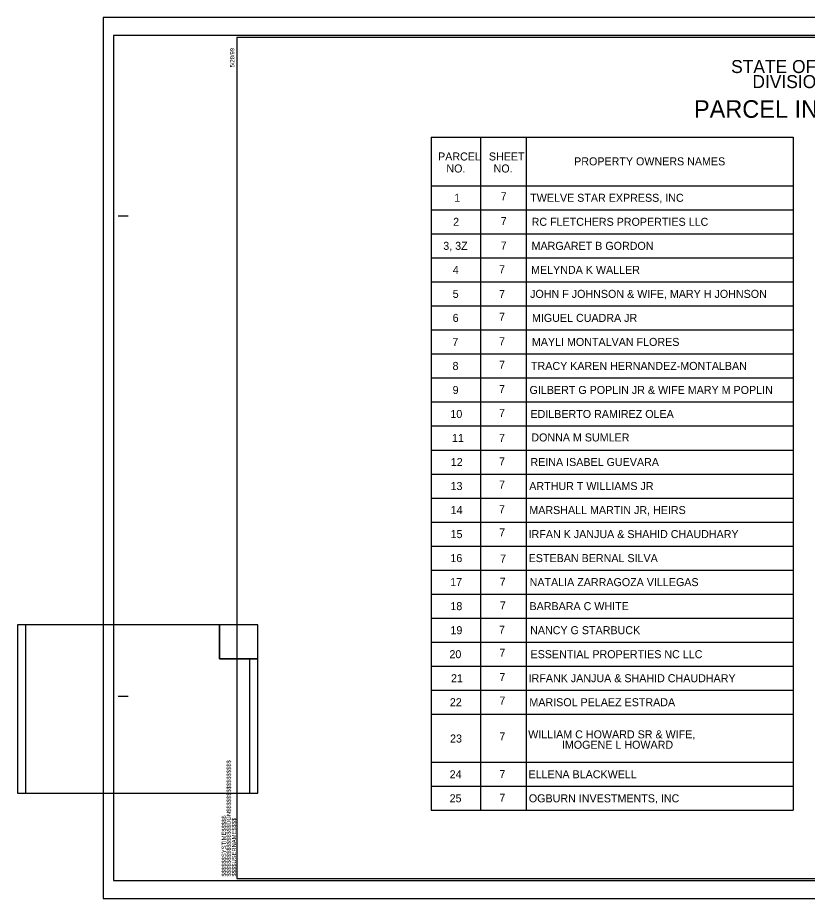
# Model space of a CAD drawing. Extents: x 1729874 to 1731665, y 539736 to 540836.
# Drawn here: x 1729874 to 1730861, y 539736 to 540836 of the extents above; entities that cross this region are included whole.
import ezdxf

# ---------------------------------------------------------------- set-up
doc = ezdxf.new("R2010")
doc.units = 0
for name, color, linetype in [('Sheet Clip Boundary CELL', 7, 'Continuous'), ('Sheet Layout Plan Border', 7, 'Continuous'), ('Sheet Plan Layout CELL', 7, 'Continuous'), ('Sheet Plot Border Inside CELL', 7, 'Continuous'), ('Sheet Plot Border Outside CELL', 7, 'Continuous'), ('Sheet Summary CELL', 7, 'Continuous')]:
    doc.layers.add(name, color=color, linetype=linetype)

msp = doc.modelspace()

# ---------------------------------------------------------------- linework, layer by layer
at = {"layer": 'Sheet Clip Boundary CELL'}
msp.add_lwpolyline([(1729884, 539867.9), (1730164, 539867.9), (1730164, 540035.6), (1730126.1, 540035.6), (1730126.1, 540077.9), (1729884, 540077.9)], close=True, dxfattribs=at)
at = {"layer": 'Sheet Layout Plan Border'}
msp.add_lwpolyline([(1729884, 539867.9), (1730164, 539867.9), (1730164, 540035.6), (1730126.1, 540035.6), (1730126.1, 540077.9), (1729884, 540077.9)], close=True, dxfattribs=at)
at = {"layer": 'Sheet Plan Layout CELL'}
for points in [[(1729874, 540077.9), (1729874, 539867.9), (1730174, 539867.9), (1730174, 540035.6), (1730126.1, 540035.6), (1730126.1, 540077.9)], [(1730126.1, 540035.6), (1730174, 540035.6), (1730174, 540077.9), (1730126.1, 540077.9)]]:
    msp.add_lwpolyline(points, close=True, dxfattribs=at)
at = {"layer": 'Sheet Plot Border Inside CELL'}
msp.add_lwpolyline([(1731660.4, 540813.9), (1729993.9, 540813.9), (1729993.9, 539758.8), (1731660.4, 539758.8)], close=True, dxfattribs=at)
at = {"layer": 'Sheet Plot Border Outside CELL'}
msp.add_lwpolyline([(1731664.9, 540836.3), (1729980.9, 540836.3), (1729980.9, 539736.3), (1731664.9, 539736.3)], close=True, dxfattribs=at)
at = {"layer": 'Sheet Summary CELL'}
for p, q in [((1730147.9, 540811.3), (1730147.9, 540770.9)), ((1730390.5, 540687.2), (1730842.6, 540687.2)), ((1730390.5, 540687.2), (1730777.1, 540687.2)), ((1730390.5, 540687.2), (1730390.5, 539846.3)), ((1730452.1, 540687.2), (1730452.1, 539846.3)), ((1730509.4, 540687.2), (1730509.4, 539846.3)), ((1730842.6, 540687.2), (1730842.6, 539846.3)), ((1730390.5, 540626.3), (1730842.6, 540626.3)), ((1730390.5, 540596.3), (1730842.6, 540596.3)), ((1729999.4, 540588.8), (1730011.9, 540588.8)), ((1730390.5, 540566.3), (1730842.6, 540566.3)), ((1730390.5, 540536.3), (1730842.6, 540536.3)), ((1730390.5, 540506.3), (1730842.6, 540506.3)), ((1730390.5, 540476.3), (1730842.6, 540476.3)), ((1730390.5, 540446.3), (1730842.6, 540446.3)), ((1730390.5, 540416.3), (1730842.6, 540416.3)), ((1730390.5, 540386.3), (1730842.6, 540386.3)), ((1730390.5, 540356.3), (1730842.6, 540356.3)), ((1730390.5, 540326.3), (1730842.6, 540326.3)), ((1730390.5, 540296.3), (1730842.6, 540296.3)), ((1730390.5, 540266.3), (1730842.6, 540266.3)), ((1730390.5, 540236.3), (1730842.6, 540236.3)), ((1730390.5, 540206.3), (1730842.6, 540206.3)), ((1730390.5, 540176.3), (1730842.6, 540176.3)), ((1730390.5, 540146.3), (1730842.6, 540146.3)), ((1730390.5, 540116.3), (1730842.6, 540116.3)), ((1730390.5, 540086.3), (1730842.6, 540086.3)), ((1730390.5, 540056.3), (1730842.6, 540056.3)), ((1730390.5, 540026.3), (1730842.6, 540026.3)), ((1730390.5, 539996.3), (1730842.6, 539996.3)), ((1729999.4, 539988.8), (1730011.9, 539988.8)), ((1730390.5, 539966.3), (1730842.6, 539966.3)), ((1730390.5, 539906.3), (1730842.6, 539906.3)), ((1730390.5, 539876.3), (1730842.6, 539876.3)), ((1730390.5, 539846.3), (1730842.6, 539846.3)), ((1730147.9, 539761.3), (1730147.9, 539761.3)), ((1730147.9, 539761.3), (1730147.9, 539761.3)), ((1730147.9, 539761.3), (1730147.9, 539761.3)), ((1730147.9, 539761.3), (1730147.9, 539761.3)), ((1730147.9, 539761.3), (1730147.9, 539761.3)), ((1730147.9, 539761.3), (1730147.9, 539761.3))]:
    msp.add_line(p, q, dxfattribs=at)
msp.add_lwpolyline([(1731647.9, 540811.3), (1730147.9, 540811.3), (1730147.9, 539761.3), (1731647.9, 539761.3)], close=True, dxfattribs=at)
msp.add_lwpolyline([(1730285.4, 539761.3), (1730285.4, 539761.3)], dxfattribs=at)

# ---------------------------------------------------------------- texts
for s, p in [('5/28/99', (1730144.7, 540774.2)), ('$$$$$$$$$$$$$$$$DGN$$$$$$$$$$$$$$$$', (1730140.3, 539763.7)), ('$$$$$$SYSTIME$$$$$', (1730134.2, 539763.7)), ('$$$$USERNAME$$$$', (1730146.9, 539763.7))]:
    msp.add_text(s, height=5.25, rotation=90, dxfattribs=at).set_placement(p)
for s, height, p in [('STATE OF NORTH CAROLINA', 16.25, (1730765.3, 540767.1)), ('DIVISION OF HIGHWAYS', 16.25, (1730791.9, 540748.3)), ('PARCEL INDEX SHEET', 21.95, (1730718.9, 540711.2)), ('PARCEL', 10, (1730399.2, 540657.9)), ('SHEET ', 10, (1730462.7, 540657.9)), ('PROPERTY OWNERS NAMES ', 10, (1730569.2, 540651.8)), ('NO. ', 10, (1730409.6, 540642.9)), ('NO.', 10, (1730468.6, 540642.9)), ('7', 10, (1730477.5, 540608.3)), ('1', 10, (1730419.3, 540606.3)), ('TWELVE STAR EXPRESS, INC', 10, (1730514.3, 540606.3)), ('2', 10, (1730418, 540576.3)), ('7', 10, (1730477.5, 540577.2)), ('RC FLETCHERS PROPERTIES LLC', 10, (1730516.1, 540576.3)), ('3, 3Z', 10, (1730405.7, 540546.3)), ('7', 10, (1730477.5, 540546.7)), ('MARGARET B GORDON', 10, (1730516, 540546.3)), ('4', 10, (1730417.6, 540516.3)), ('7', 10, (1730475.4, 540517)), ('MELYNDA K WALLER', 10, (1730515.4, 540516.3)), ('5', 10, (1730417.5, 540486.3)), ('7', 10, (1730475.4, 540486)), ('JOHN F JOHNSON & WIFE, MARY H JOHNSON', 10, (1730514.2, 540486.3)), ('6', 10, (1730417.4, 540456.3)), ('7', 10, (1730475.4, 540457.7)), ('MIGUEL CUADRA JR', 10, (1730516.5, 540456.3)), ('7', 10, (1730417.1, 540426.3)), ('7', 10, (1730475.4, 540427.2)), ('MAYLI MONTALVAN FLORES', 10, (1730516.4, 540426.3)), ('8', 10, (1730417.3, 540396.3)), ('7', 10, (1730475.4, 540397.7)), ('TRACY KAREN HERNANDEZ-MONTALBAN', 10, (1730515.3, 540396.3)), ('9', 10, (1730417.4, 540366.3)), ('7', 10, (1730475.4, 540367.5)), ('GILBERT G POPLIN JR & WIFE MARY M POPLIN', 10, (1730513.5, 540366.3)), ('10', 10, (1730414.6, 540336.3)), ('7', 10, (1730475.4, 540337.7)), ('EDILBERTO RAMIREZ OLEA', 10, (1730514.6, 540336.3)), ('11', 10, (1730416.6, 540306.3)), ('7', 10, (1730475.4, 540306.5)), ('DONNA M SUMLER', 10, (1730515.7, 540307)), ('7', 10, (1730475.4, 540277.1)), ('12', 10, (1730415.1, 540276.3)), ('REINA ISABEL GUEVARA', 10, (1730514.6, 540276.3)), ('13', 10, (1730414.8, 540246.3)), ('7', 10, (1730475.4, 540248.2)), ('ARTHUR T WILLIAMS JR', 10, (1730513.1, 540246.3)), ('14', 10, (1730414.9, 540216.3)), ('7', 10, (1730475.3, 540217.3)), ('MARSHALL MARTIN JR, HEIRS', 10, (1730513.2, 540216.3)), ('15', 10, (1730414.8, 540186.3)), ('7', 10, (1730475.5, 540188.3)), ('IRFAN K JANJUA & SHAHID CHAUDHARY', 10, (1730512.3, 540186.3)), ('16', 10, (1730414.6, 540156.3)), ('ESTEBAN BERNAL SILVA', 10, (1730512.4, 540156.3)), ('7', 10, (1730476.7, 540155.7)), ('17', 10, (1730414.3, 540126.3)), ('7', 10, (1730476.2, 540126.8)), ('NATALIA ZARRAGOZA VILLEGAS', 10, (1730513.6, 540126.3)), ('18', 10, (1730414.6, 540096.3)), ('7', 10, (1730476.4, 540097.2)), ('BARBARA C WHITE', 10, (1730513.4, 540096.3)), ('19', 10, (1730414.7, 540066.3)), ('7', 10, (1730475.3, 540066.9)), ('NANCY G STARBUCK', 10, (1730514.2, 540066.3)), ('20', 10, (1730413.4, 540036.3)), ('7', 10, (1730475.8, 540038.1)), ('ESSENTIAL PROPERTIES NC LLC', 10, (1730514.7, 540036.3)), ('21', 10, (1730415.4, 540006.3)), ('7', 10, (1730475.8, 540007.8)), ('IRFANK JANJUA & SHAHID CHAUDHARY', 10, (1730512.3, 540006.3)), ('22', 10, (1730413.9, 539976.3)), ('7', 10, (1730475.8, 539978.4)), ('MARISOL PELAEZ ESTRADA', 10, (1730513.3, 539976.3)), ('WILLIAM C HOWARD SR & WIFE,', 10, (1730511.8, 539936.2)), ('23', 10, (1730414.2, 539931)), ('7', 10, (1730475.8, 539933.7)), ('IMOGENE L HOWARD', 10, (1730553.9, 539923.2)), ('24', 10, (1730413.7, 539886.3)), ('7', 10, (1730475.8, 539886.6)), ('ELLENA BLACKWELL', 10, (1730512.2, 539886.3)), ('25', 10, (1730413.6, 539856.3)), ('7', 10, (1730475.8, 539857.1)), ('OGBURN INVESTMENTS, INC', 10, (1730512.6, 539856.3))]:
    msp.add_text(s, height=height, dxfattribs=at).set_placement(p)

doc.saveas('drawing.dxf')
